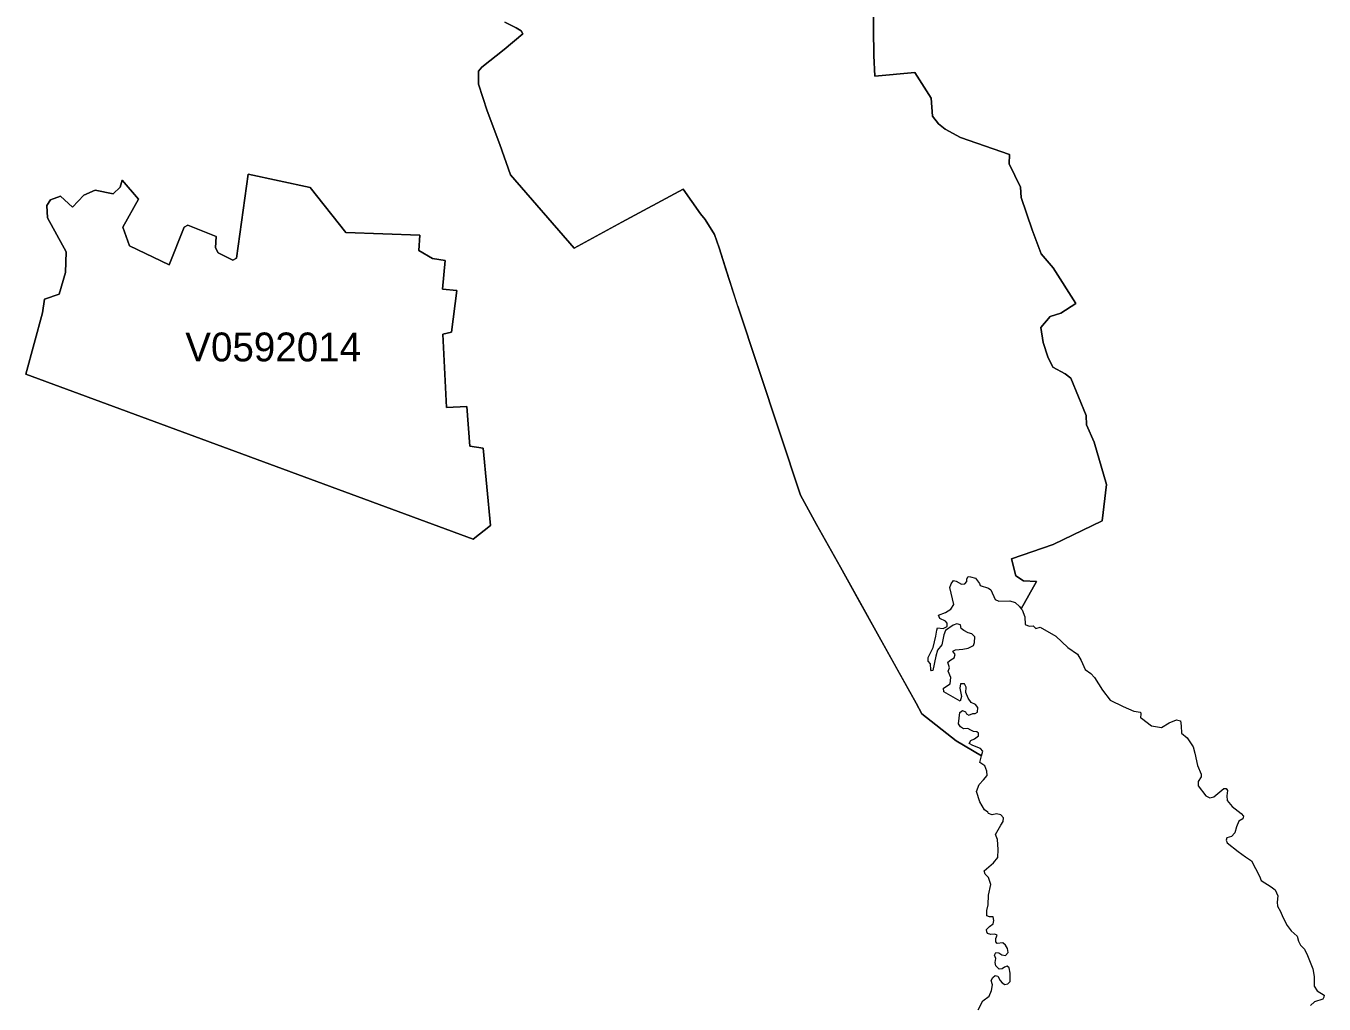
# Model space of a CAD drawing. Extents: x 369010 to 735936, y 6377141 to 6616555.
# Drawn here: x 429772 to 434273, y 6465746 to 6469139 of the extents above; entities that cross this region are included whole.
import ezdxf
from ezdxf.enums import TextEntityAlignment as Align

# ---------------------------------------------------------------- set-up
doc = ezdxf.new("R2010")
doc.units = 0
doc.header["$LTSCALE"] = 40
doc.layers.add('3', color=7, linetype='Continuous', lineweight=13)
doc.layers.add('4', color=7, linetype='Continuous')

msp = doc.modelspace()

# ---------------------------------------------------------------- linework, layer by layer
at = {"layer": '3'}
for points in [[(432709.55, 6469217.65), (432712.2, 6469036.75), (432716.01, 6468965.09), (432853.7, 6468976.84), (432910.64, 6468887.96), (432915.77, 6468825.57), (432936.62, 6468799.42), (432958.8, 6468781.21), (433012.59, 6468751.92), (433182.73, 6468693.33), (433181.4, 6468660.89), (433220.46, 6468580.13), (433223.11, 6468543.72), (433260.84, 6468431.01), (433292.12, 6468347.76), (433333.67, 6468299.6), (433412.28, 6468176.13), (433360.31, 6468142.2), (433323.9, 6468130.45), (433291.46, 6468092.72), (433299.24, 6468040.75), (433314.8, 6467991.26), (433332.67, 6467955.02), (433375.7, 6467931.52), (433395.07, 6467917.28), (433448.36, 6467787.2), (433449.02, 6467755.75), (433476.33, 6467694.68), (433518.87, 6467548.04), (433503.31, 6467421.76), (433333.5, 6467340.17), (433189.18, 6467290.68), (433204.9, 6467230.94), (433230.89, 6467214.06), (433276.24, 6467211.41), (433223.27, 6467117.07)], [(432932.32, 6466973.25), (432926.53, 6466952.56), (432916.1, 6466902.91), (432911.63, 6466901.75), (432909.31, 6466905.23), (432908.16, 6466925.91), (432900.05, 6466935.18), (432900.05, 6466947.93), (432917.26, 6466982.52), (432926.53, 6467021.74), (432930, 6467042.59), (432932.32, 6467050.7), (432952.01, 6467048.39), (432965.75, 6467055.34), (432965.75, 6467066.76), (432959.96, 6467073.71), (432940.43, 6467082.98), (432935.79, 6467094.56), (432959.96, 6467103.83), (432978.49, 6467115.25), (432988.92, 6467131.47), (432975.02, 6467190.39), (432979.65, 6467204.13), (432987.76, 6467215.71), (432998.02, 6467213.39), (433015.4, 6467201.97), (433026.99, 6467204.13), (433033.94, 6467212.24), (433033.94, 6467221.5), (433039.57, 6467229.61), (433047.68, 6467228.45), (433065.05, 6467223.82), (433077.8, 6467205.28), (433081.11, 6467197.34), (433110.07, 6467188.07), (433118.18, 6467182.28), (433133.08, 6467148.85), (433145.82, 6467143.05), (433183.88, 6467144.21), (433202.42, 6467138.42), (433217.32, 6467124.52), (433223.27, 6467117.07), (433276.24, 6467211.41), (433230.89, 6467214.06), (433204.9, 6467230.94), (433189.18, 6467290.68), (433333.5, 6467340.17), (433503.31, 6467421.76), (433518.87, 6467548.04), (433476.33, 6467694.68), (433449.02, 6467755.75), (433448.36, 6467787.2), (433395.07, 6467917.28), (433375.7, 6467931.52), (433332.67, 6467955.02), (433314.8, 6467991.26), (433299.24, 6468040.75), (433291.46, 6468092.72), (433323.9, 6468130.45), (433360.31, 6468142.2), (433412.28, 6468176.13), (433333.67, 6468299.6), (433292.12, 6468347.76), (433260.84, 6468431.01), (433223.11, 6468543.72), (433220.46, 6468580.13), (433181.4, 6468660.89), (433182.73, 6468693.33), (433012.59, 6468751.92), (432958.8, 6468781.21), (432936.62, 6468799.42), (432915.77, 6468825.57), (432910.64, 6468887.96), (432853.7, 6468976.84), (432716.01, 6468965.09), (432712.2, 6469036.75), (432709.55, 6469217.65)], [(431432.52, 6469152.44), (431471.42, 6469132.58), (431489.29, 6469121.66), (431494.59, 6469110.9), (431430.2, 6469057.44), (431352.91, 6468996.04), (431341.33, 6468982.47), (431340.83, 6468936.95), (431371.45, 6468844.6), (431415.47, 6468727.09), (431452.71, 6468622.83), (431672.67, 6468368.45), (431838.83, 6468458.65), (432050.51, 6468573.01), (432111.58, 6468487.11), (432127.31, 6468467.42), (432159.25, 6468415.95), (432175.3, 6468369.27), (432175.63, 6468368.61), (432239.68, 6468168.19), (432240.02, 6468166.86), (432457.98, 6467510.64), (432513.26, 6467409.35), (432596.35, 6467261.39), (432596.51, 6467260.89), (432794.29, 6466904.89), (432858.5, 6466789.7), (432878.53, 6466753.29), (432997.53, 6466659.12), (433085.58, 6466606.82), (433089.55, 6466623.04), (433081.77, 6466632.14), (433055.78, 6466642.57), (433042.88, 6466650.35), (433048.01, 6466660.78), (433060.92, 6466665.91), (433075.31, 6466676.33), (433075.31, 6466685.44), (433068.86, 6466690.57), (433057.11, 6466691.89), (433048.01, 6466695.86), (433037.58, 6466702.32), (433023.35, 6466700.99), (433012.92, 6466707.45), (433005.14, 6466717.88), (433010.44, 6466756.93), (433019.37, 6466764.71), (433029.8, 6466759.42), (433033.77, 6466752.96), (433041.55, 6466747.83), (433055.78, 6466754.29), (433063.56, 6466754.29), (433071.34, 6466758.09), (433072.67, 6466774.97), (433064.89, 6466785.4), (433049.33, 6466791.86), (433038.9, 6466807.58), (433031.12, 6466826.94), (433032.45, 6466845.15), (433025.99, 6466856.9), (433012.92, 6466856.9), (433010.44, 6466841.34), (433015.57, 6466812.71), (433011.6, 6466797.15), (432954.5, 6466829.59), (432953.17, 6466841.34), (432976.67, 6466856.9), (432979.16, 6466878.91), (432970.05, 6466901.09), (432974.03, 6466912.67), (432968.9, 6466932.2), (432979.16, 6466939.98), (432990.91, 6466946.44), (432993.56, 6466958.19), (432985.78, 6466969.94), (432994.71, 6466975.07), (433020.04, 6466976.72), (433038.57, 6466980.2), (433058.1, 6466989.47), (433061.58, 6466999.89), (433062.74, 6467019.42), (433052.31, 6467029.85), (433038.57, 6467033.33), (433023.51, 6467041.44), (433014.24, 6467048.39), (433011.93, 6467060.96), (433000.34, 6467064.44), (432986.6, 6467059.97), (432959.96, 6467041.44), (432954.33, 6467026.37), (432947.38, 6466991.78), (432932.32, 6466973.25)], [(431494.59, 6469110.9), (431489.29, 6469121.66), (431471.42, 6469132.58), (431432.52, 6469152.44)], [(433090.21, 6465757.29), (433112.06, 6465773.84), (433119.83, 6465793.04), (433123.48, 6465812.24), (433118.51, 6465828.29), (433124.14, 6465837.89), (433133.24, 6465844.51), (433141.52, 6465842.36), (433150.29, 6465828.29), (433156.74, 6465819.19), (433165.85, 6465813.56), (433176.44, 6465816.21), (433184.71, 6465824.82), (433184.71, 6465853.12), (433181.07, 6465871.82), (433174.62, 6465877.94), (433164.52, 6465873.97), (433156.74, 6465867.85), (433146.32, 6465866.69), (433134.56, 6465878.94), (433132.25, 6465889.69), (433135.39, 6465903.76), (433130.59, 6465915.84), (433134.56, 6465925.11), (433144.99, 6465923.29), (433155.42, 6465916.84), (433168, 6465914.19), (433177.6, 6465925.11), (433175.94, 6465938.52), (433168.49, 6465950.27), (433159.39, 6465958.54), (433140.03, 6465955.73), (433134.73, 6465962.18), (433135.23, 6465973.11), (433139.2, 6465984.53), (433131.25, 6465988.83), (433117.85, 6465987.01), (433105.6, 6465990.98), (433103.45, 6465996.61), (433102.62, 6466004.55), (433112.55, 6466015.48), (433125.96, 6466024.25), (433128.28, 6466036), (433125.63, 6466048.58), (433113.21, 6466048.08), (433103.28, 6466051.56), (433103.62, 6466071.09), (433108.42, 6466089.79), (433109.57, 6466123.88), (433117.85, 6466161.12), (433109.24, 6466185.12), (433098.32, 6466196.87), (433094.35, 6466208.45), (433126.46, 6466236.09), (433141.68, 6466254.46), (433142.67, 6466282.43), (433140.19, 6466316.36), (433133.74, 6466333.74), (433152.11, 6466366.51), (433159.89, 6466379.09), (433161.71, 6466391.83), (433152.11, 6466402.59), (433136.88, 6466406.07), (433121.99, 6466402.59), (433109.41, 6466406.56), (433106.76, 6466411.36), (433095.51, 6466419.47), (433078.96, 6466447.77), (433068.53, 6466483.85), (433077.3, 6466507.35), (433091.7, 6466523.41), (433104.77, 6466538.8), (433104.28, 6466553.36), (433097, 6466572.73), (433079.12, 6466583.65), (433085.58, 6466606.82), (432997.53, 6466659.12), (432878.53, 6466753.29), (432858.5, 6466789.7), (432657.58, 6467150.17), (432596.35, 6467261.39), (432513.26, 6467409.35), (432457.98, 6467510.64), (432240.02, 6468166.86), (432198.81, 6468295.62), (432175.3, 6468369.27), (432159.25, 6468415.95), (432127.31, 6468467.42), (432111.58, 6468487.11), (432050.51, 6468573.01), (431838.83, 6468458.65), (431672.67, 6468368.45), (431452.71, 6468622.83), (431415.47, 6468727.09), (431371.45, 6468844.6), (431340.83, 6468936.95), (431341.33, 6468982.47), (431352.91, 6468996.04), (431430.2, 6469057.44), (431494.59, 6469110.9)], [(433223.27, 6467117.07), (433226.59, 6467112.93), (433235.85, 6467088.77), (433237.01, 6467062.12), (433250.75, 6467056.5), (433264.65, 6467057.65), (433273.92, 6467048.39), (433288.81, 6467053.02), (433343.1, 6467021.74), (433384.64, 6466982.52), (433418.07, 6466959.51), (433430.82, 6466937.5), (433444.72, 6466906.38), (433464.25, 6466892.48), (433476.99, 6466878.58), (433504.63, 6466834.72), (433531.28, 6466800.13), (433576.13, 6466778.12), (433613.2, 6466762.06), (433636.21, 6466758.59), (433637.37, 6466752.8), (433636.21, 6466738.89), (433639.68, 6466737.74), (433674.77, 6466711.25), (433709.36, 6466705.46), (433735.84, 6466721.68), (433761.33, 6466731.94), (433775.07, 6466728.47), (433777.38, 6466711.25), (433778.54, 6466685.77), (433798.24, 6466669.71), (433818.92, 6466638.43), (433824.72, 6466616.59), (433833.98, 6466573.89), (433846.73, 6466543.76), (433846.73, 6466534.66), (433836.3, 6466518.44), (433836.3, 6466503.38), (433862.78, 6466467.8), (433876.68, 6466460.85), (433890.59, 6466464.32), (433925.18, 6466493.29), (433933.29, 6466493.29), (433937.76, 6466486.33), (433935.44, 6466467.8), (433936.76, 6466451.74), (433953.98, 6466430.89), (433985.09, 6466406.73), (433993.2, 6466397.46), (433990.88, 6466388.19), (433976.98, 6466380.08), (433969.04, 6466360.55), (433963.24, 6466339.7), (433951.66, 6466326.95), (433935.44, 6466322.32), (433933.29, 6466314.38), (433936.76, 6466305.11), (433974.83, 6466274.99), (434000.15, 6466256.62), (434021.34, 6466243.38), (434049.14, 6466189.09), (434054.77, 6466174.19), (434089.36, 6466152.18), (434103.26, 6466141.76), (434112.53, 6466121.07), (434110.21, 6466099.06), (434111.37, 6466085.32), (434121.8, 6466066.78), (434129.91, 6466047.09), (434144.8, 6466018.46), (434158.7, 6466000.08), (434179.39, 6465981.55), (434184.03, 6465964.17), (434190.98, 6465950.43), (434204.88, 6465936.53), (434215.14, 6465914.52), (434233.68, 6465868.34), (434238.31, 6465841.86), (434238.31, 6465808.43), (434248.74, 6465792.21), (434272.9, 6465777.15), (434271.74, 6465770.36), (434268.27, 6465763.41), (434239.47, 6465754.15), (434225.57, 6465741.4)], [(433074.16, 6465726.01), (433090.21, 6465757.29)]]:
    msp.add_lwpolyline(points, dxfattribs=at)
for points in [[(429772.35, 6467930.85), (429830.11, 6468143.53), (429836.57, 6468191.52), (429887.21, 6468208.4), (429909.39, 6468283.87), (429912.04, 6468355.21), (429846.99, 6468473.54), (429844.51, 6468516.41), (429857.42, 6468535.94), (429892.51, 6468548.85), (429934.05, 6468509.95), (429972.94, 6468551.49), (430012, 6468569.7), (430074.23, 6468556.62), (430099.06, 6468580.13), (430105.51, 6468603.46), (430162.61, 6468538.42), (430107.99, 6468441.1), (430131.49, 6468376.06), (430268.37, 6468309.86), (430320.33, 6468441.1), (430333.24, 6468447.56), (430431.88, 6468408.66), (430429.4, 6468369.6), (430438.5, 6468351.57), (430489.15, 6468326.74), (430502.06, 6468333.36), (430542.28, 6468624.32), (430757.93, 6468578.8), (430881.39, 6468422.24), (431138.42, 6468413.13), (431134.61, 6468359.84), (431181.29, 6468332.7), (431225.48, 6468324.75), (431216.37, 6468226.11), (431265.69, 6468220.82), (431247.98, 6468076.99), (431218.19, 6468069.22), (431229.94, 6467815.83), (431301.28, 6467818.48), (431311.54, 6467680.94), (431357.05, 6467674.49), (431383.04, 6467405.54), (431323.29, 6467358.71)], [(429772.35, 6467930.85), (431323.29, 6467358.71), (431383.04, 6467405.54), (431357.05, 6467674.49), (431311.54, 6467680.94), (431301.28, 6467818.48), (431229.94, 6467815.83), (431218.19, 6468069.22), (431247.98, 6468076.99), (431265.69, 6468220.82), (431216.37, 6468226.11), (431225.48, 6468324.75), (431181.29, 6468332.7), (431134.61, 6468359.84), (431138.42, 6468413.13), (430881.39, 6468422.24), (430757.93, 6468578.8), (430542.28, 6468624.32), (430502.06, 6468333.36), (430489.15, 6468326.74), (430438.5, 6468351.57), (430429.4, 6468369.6), (430431.88, 6468408.66), (430333.24, 6468447.56), (430320.33, 6468441.1), (430268.37, 6468309.86), (430131.49, 6468376.06), (430107.99, 6468441.1), (430162.61, 6468538.42), (430105.51, 6468603.46), (430099.06, 6468580.13), (430074.23, 6468556.62), (430012, 6468569.7), (429972.94, 6468551.49), (429934.05, 6468509.95), (429892.51, 6468548.85), (429857.42, 6468535.94), (429844.51, 6468516.41), (429846.99, 6468473.54), (429912.04, 6468355.21), (429909.39, 6468283.87), (429887.21, 6468208.4), (429836.57, 6468191.52), (429830.11, 6468143.53)]]:
    msp.add_lwpolyline(points, close=True, dxfattribs=at)

# ---------------------------------------------------------------- texts
at = {"layer": '4'}
msp.add_text('V0592014', height=100, dxfattribs=at).set_placement((430629.49, 6467975.34), align=Align.CENTER)

doc.saveas('drawing.dxf')
